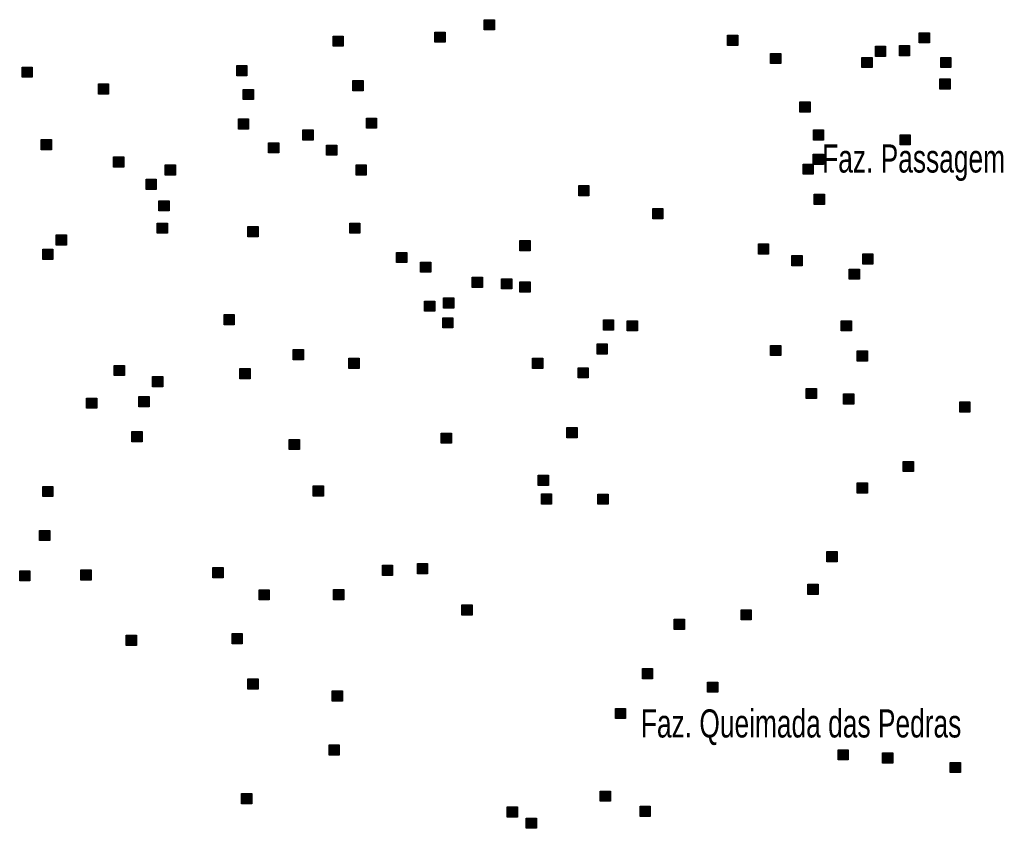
# Model space of a CAD drawing. Extents: x 445.4 to 500, y 8728.7 to 8784.
# Drawn here: x 452.93 to 458.52, y 8728.69 to 8733.29 of the extents above; entities that cross this region are included whole.
import ezdxf

# ---------------------------------------------------------------- set-up
doc = ezdxf.new("R2010")
doc.units = 0
doc.header["$LTSCALE"] = 0.064
doc.layers.add('2', color=7, linetype='Continuous', lineweight=25)
doc.layers.add('61', color=7, linetype='Continuous')

msp = doc.modelspace()

# ---------------------------------------------------------------- hatches: boundary and pattern name
at = {"layer": '2'}
for points in [[(455.5694, 8733.2875), (455.6274, 8733.2875), (455.6274, 8733.2295), (455.5694, 8733.2295)], [(454.7097, 8733.1942), (454.7677, 8733.1942), (454.7677, 8733.1362), (454.7097, 8733.1362)], [(455.2889, 8733.2168), (455.3469, 8733.2168), (455.3469, 8733.1588), (455.2889, 8733.1588)], [(456.9541, 8733.1994), (457.0121, 8733.1994), (457.0121, 8733.1414), (456.9541, 8733.1414)], [(458.0446, 8733.213), (458.1026, 8733.213), (458.1026, 8733.155), (458.0446, 8733.155)], [(457.7957, 8733.1361), (457.8537, 8733.1361), (457.8537, 8733.0781), (457.7957, 8733.0781)], [(457.9315, 8733.1406), (457.9895, 8733.1406), (457.9895, 8733.0826), (457.9315, 8733.0826)], [(457.1984, 8733.0953), (457.2564, 8733.0953), (457.2564, 8733.0373), (457.1984, 8733.0373)], [(454.1622, 8733.0266), (454.2202, 8733.0266), (454.2202, 8732.9686), (454.1622, 8732.9686)], [(457.7188, 8733.0727), (457.7768, 8733.0727), (457.7768, 8733.0147), (457.7188, 8733.0147)], [(458.1668, 8733.0727), (458.2248, 8733.0727), (458.2248, 8733.0147), (458.1668, 8733.0147)], [(452.9406, 8733.0176), (452.9986, 8733.0176), (452.9986, 8732.9596), (452.9406, 8732.9596)], [(453.3749, 8732.9225), (453.4329, 8732.9225), (453.4329, 8732.8645), (453.3749, 8732.8645)], [(454.8229, 8732.9406), (454.8809, 8732.9406), (454.8809, 8732.8826), (454.8229, 8732.8826)], [(458.1623, 8732.9504), (458.2203, 8732.9504), (458.2203, 8732.8924), (458.1623, 8732.8924)], [(454.1984, 8732.8908), (454.2564, 8732.8908), (454.2564, 8732.8328), (454.1984, 8732.8328)], [(457.3659, 8732.8191), (457.4239, 8732.8191), (457.4239, 8732.7611), (457.3659, 8732.7611)], [(454.1713, 8732.7233), (454.2293, 8732.7233), (454.2293, 8732.6653), (454.1713, 8732.6653)], [(454.8998, 8732.7278), (454.9578, 8732.7278), (454.9578, 8732.6698), (454.8998, 8732.6698)], [(454.5378, 8732.6599), (454.5958, 8732.6599), (454.5958, 8732.6019), (454.5378, 8732.6019)], [(457.4428, 8732.6607), (457.5008, 8732.6607), (457.5008, 8732.6027), (457.4428, 8732.6027)], [(457.9354, 8732.6324), (457.9934, 8732.6324), (457.9934, 8732.5744), (457.9354, 8732.5744)], [(453.0492, 8732.6056), (453.1072, 8732.6056), (453.1072, 8732.5476), (453.0492, 8732.5476)], [(454.3432, 8732.5875), (454.4012, 8732.5875), (454.4012, 8732.5295), (454.3432, 8732.5295)], [(454.6735, 8732.5739), (454.7315, 8732.5739), (454.7315, 8732.5159), (454.6735, 8732.5159)], [(457.4413, 8732.5219), (457.4993, 8732.5219), (457.4993, 8732.4639), (457.4413, 8732.4639)], [(453.4609, 8732.506), (453.5189, 8732.506), (453.5189, 8732.448), (453.4609, 8732.448)], [(457.384, 8732.466), (457.442, 8732.466), (457.442, 8732.408), (457.384, 8732.408)], [(453.755, 8732.4607), (453.813, 8732.4607), (453.813, 8732.4027), (453.755, 8732.4027)], [(454.841, 8732.4607), (454.899, 8732.4607), (454.899, 8732.4027), (454.841, 8732.4027)], [(453.6464, 8732.3792), (453.7044, 8732.3792), (453.7044, 8732.3212), (453.6464, 8732.3212)], [(456.1079, 8732.3438), (456.1659, 8732.3438), (456.1659, 8732.2858), (456.1079, 8732.2858)], [(453.7188, 8732.257), (453.7768, 8732.257), (453.7768, 8732.199), (453.7188, 8732.199)], [(457.4473, 8732.294), (457.5053, 8732.294), (457.5053, 8732.236), (457.4473, 8732.236)], [(456.5287, 8732.2125), (456.5867, 8732.2125), (456.5867, 8732.1545), (456.5287, 8732.1545)], [(453.7098, 8732.1302), (453.7678, 8732.1302), (453.7678, 8732.0722), (453.7098, 8732.0722)], [(454.8048, 8732.1302), (454.8628, 8732.1302), (454.8628, 8732.0722), (454.8048, 8732.0722)], [(454.2258, 8732.1099), (454.2838, 8732.1099), (454.2838, 8732.0519), (454.2258, 8732.0519)], [(453.1351, 8732.0623), (453.1931, 8732.0623), (453.1931, 8732.0043), (453.1351, 8732.0043)], [(455.773, 8732.0306), (455.831, 8732.0306), (455.831, 8731.9726), (455.773, 8731.9726)], [(453.0582, 8731.9808), (453.1162, 8731.9808), (453.1162, 8731.9228), (453.0582, 8731.9228)], [(455.0717, 8731.9627), (455.1297, 8731.9627), (455.1297, 8731.9047), (455.0717, 8731.9047)], [(457.1296, 8732.0111), (457.1876, 8732.0111), (457.1876, 8731.9531), (457.1296, 8731.9531)], [(455.2075, 8731.9084), (455.2655, 8731.9084), (455.2655, 8731.8504), (455.2075, 8731.8504)], [(457.3206, 8731.9453), (457.3786, 8731.9453), (457.3786, 8731.8873), (457.3206, 8731.8873)], [(457.7233, 8731.9544), (457.7813, 8731.9544), (457.7813, 8731.8964), (457.7233, 8731.8964)], [(457.6464, 8731.8684), (457.7044, 8731.8684), (457.7044, 8731.8104), (457.6464, 8731.8104)], [(455.5016, 8731.8223), (455.5596, 8731.8223), (455.5596, 8731.7643), (455.5016, 8731.7643)], [(455.669, 8731.8133), (455.727, 8731.8133), (455.727, 8731.7553), (455.669, 8731.7553)], [(455.773, 8731.7952), (455.831, 8731.7952), (455.831, 8731.7372), (455.773, 8731.7372)], [(455.2301, 8731.6865), (455.2881, 8731.6865), (455.2881, 8731.6285), (455.2301, 8731.6285)], [(455.3387, 8731.7046), (455.3967, 8731.7046), (455.3967, 8731.6466), (455.3387, 8731.6466)], [(454.0899, 8731.6096), (454.1479, 8731.6096), (454.1479, 8731.5516), (454.0899, 8731.5516)], [(455.3341, 8731.5914), (455.3921, 8731.5914), (455.3921, 8731.5334), (455.3341, 8731.5334)], [(456.2482, 8731.5786), (456.3062, 8731.5786), (456.3062, 8731.5206), (456.2482, 8731.5206)], [(456.3839, 8731.5741), (456.4419, 8731.5741), (456.4419, 8731.5161), (456.3839, 8731.5161)], [(457.6012, 8731.5741), (457.6592, 8731.5741), (457.6592, 8731.5161), (457.6012, 8731.5161)], [(454.4835, 8731.4103), (454.5415, 8731.4103), (454.5415, 8731.3523), (454.4835, 8731.3523)], [(456.212, 8731.4428), (456.27, 8731.4428), (456.27, 8731.3848), (456.212, 8731.3848)], [(457.1984, 8731.4337), (457.2564, 8731.4337), (457.2564, 8731.3757), (457.1984, 8731.3757)], [(457.6917, 8731.4021), (457.7497, 8731.4021), (457.7497, 8731.3441), (457.6917, 8731.3441)], [(454.8002, 8731.3605), (454.8582, 8731.3605), (454.8582, 8731.3025), (454.8002, 8731.3025)], [(455.8454, 8731.3605), (455.9034, 8731.3605), (455.9034, 8731.3025), (455.8454, 8731.3025)], [(453.4654, 8731.3198), (453.5234, 8731.3198), (453.5234, 8731.2618), (453.4654, 8731.2618)], [(454.1803, 8731.3017), (454.2383, 8731.3017), (454.2383, 8731.2437), (454.1803, 8731.2437)], [(456.1034, 8731.307), (456.1614, 8731.307), (456.1614, 8731.249), (456.1034, 8731.249)], [(453.6826, 8731.2564), (453.7406, 8731.2564), (453.7406, 8731.1984), (453.6826, 8731.1984)], [(457.4021, 8731.1893), (457.4601, 8731.1893), (457.4601, 8731.1313), (457.4021, 8731.1313)], [(453.3071, 8731.1342), (453.3651, 8731.1342), (453.3651, 8731.0762), (453.3071, 8731.0762)], [(453.6057, 8731.1432), (453.6637, 8731.1432), (453.6637, 8731.0852), (453.6057, 8731.0852)], [(457.6147, 8731.1576), (457.6727, 8731.1576), (457.6727, 8731.0996), (457.6147, 8731.0996)], [(458.2754, 8731.1123), (458.3334, 8731.1123), (458.3334, 8731.0543), (458.2754, 8731.0543)], [(456.04, 8730.9667), (456.098, 8730.9667), (456.098, 8730.9087), (456.04, 8730.9087)], [(453.565, 8730.944), (453.623, 8730.944), (453.623, 8730.886), (453.565, 8730.886)], [(454.4609, 8730.8987), (454.5189, 8730.8987), (454.5189, 8730.8407), (454.4609, 8730.8407)], [(455.3251, 8730.935), (455.3831, 8730.935), (455.3831, 8730.877), (455.3251, 8730.877)], [(457.9541, 8730.7737), (458.0121, 8730.7737), (458.0121, 8730.7157), (457.9541, 8730.7157)], [(455.8771, 8730.695), (455.9351, 8730.695), (455.9351, 8730.637), (455.8771, 8730.637)], [(453.0582, 8730.6316), (453.1162, 8730.6316), (453.1162, 8730.5736), (453.0582, 8730.5736)], [(454.5966, 8730.6344), (454.6546, 8730.6344), (454.6546, 8730.5764), (454.5966, 8730.5764)], [(457.6917, 8730.6515), (457.7497, 8730.6515), (457.7497, 8730.5935), (457.6917, 8730.5935)], [(455.8952, 8730.5891), (455.9532, 8730.5891), (455.9532, 8730.5311), (455.8952, 8730.5311)], [(456.2165, 8730.5881), (456.2745, 8730.5881), (456.2745, 8730.5301), (456.2165, 8730.5301)], [(453.0401, 8730.3808), (453.0981, 8730.3808), (453.0981, 8730.3228), (453.0401, 8730.3228)], [(457.5197, 8730.2604), (457.5777, 8730.2604), (457.5777, 8730.2024), (457.5197, 8730.2024)], [(454.9903, 8730.1834), (455.0483, 8730.1834), (455.0483, 8730.1254), (454.9903, 8730.1254)], [(455.1894, 8730.1925), (455.2474, 8730.1925), (455.2474, 8730.1345), (455.1894, 8730.1345)], [(452.927, 8730.1517), (452.985, 8730.1517), (452.985, 8730.0937), (452.927, 8730.0937)], [(453.2754, 8730.1562), (453.3334, 8730.1562), (453.3334, 8730.0982), (453.2754, 8730.0982)], [(454.0265, 8730.1698), (454.0845, 8730.1698), (454.0845, 8730.1118), (454.0265, 8730.1118)], [(457.4111, 8730.0747), (457.4691, 8730.0747), (457.4691, 8730.0167), (457.4111, 8730.0167)], [(454.2889, 8730.0431), (454.3469, 8730.0431), (454.3469, 8729.9851), (454.2889, 8729.9851)], [(454.713, 8730.0445), (454.771, 8730.0445), (454.771, 8729.9865), (454.713, 8729.9865)], [(455.4427, 8729.957), (455.5007, 8729.957), (455.5007, 8729.899), (455.4427, 8729.899)], [(457.031, 8729.9298), (457.089, 8729.9298), (457.089, 8729.8718), (457.031, 8729.8718)], [(456.6509, 8729.8755), (456.7089, 8729.8755), (456.7089, 8729.8175), (456.6509, 8729.8175)], [(453.5333, 8729.785), (453.5913, 8729.785), (453.5913, 8729.727), (453.5333, 8729.727)], [(454.1351, 8729.7941), (454.1931, 8729.7941), (454.1931, 8729.7361), (454.1351, 8729.7361)], [(456.4699, 8729.5948), (456.5279, 8729.5948), (456.5279, 8729.5368), (456.4699, 8729.5368)], [(454.2256, 8729.536), (454.2836, 8729.536), (454.2836, 8729.478), (454.2256, 8729.478)], [(456.841, 8729.5179), (456.899, 8729.5179), (456.899, 8729.4599), (456.841, 8729.4599)], [(454.7052, 8729.4681), (454.7632, 8729.4681), (454.7632, 8729.4101), (454.7052, 8729.4101)], [(456.3161, 8729.3684), (456.3741, 8729.3684), (456.3741, 8729.3104), (456.3161, 8729.3104)], [(454.6871, 8729.1602), (454.7451, 8729.1602), (454.7451, 8729.1022), (454.6871, 8729.1022)], [(457.5831, 8729.133), (457.6411, 8729.133), (457.6411, 8729.075), (457.5831, 8729.075)], [(457.8365, 8729.1149), (457.8945, 8729.1149), (457.8945, 8729.0569), (457.8365, 8729.0569)], [(458.2211, 8729.0606), (458.2791, 8729.0606), (458.2791, 8729.0026), (458.2211, 8729.0026)], [(454.1894, 8728.884), (454.2474, 8728.884), (454.2474, 8728.826), (454.1894, 8728.826)], [(456.2301, 8728.8976), (456.2881, 8728.8976), (456.2881, 8728.8396), (456.2301, 8728.8396)], [(455.7006, 8728.8071), (455.7586, 8728.8071), (455.7586, 8728.7491), (455.7006, 8728.7491)], [(456.4563, 8728.8116), (456.5143, 8728.8116), (456.5143, 8728.7536), (456.4563, 8728.7536)], [(455.8092, 8728.7437), (455.8672, 8728.7437), (455.8672, 8728.6857), (455.8092, 8728.6857)]]:
    msp.add_hatch(color=256, dxfattribs=at).paths.add_polyline_path(points)

# ---------------------------------------------------------------- linework, layer by layer
for points in [[(455.5694, 8733.2875), (455.6274, 8733.2875), (455.6274, 8733.2295), (455.5694, 8733.2295)], [(454.7097, 8733.1942), (454.7677, 8733.1942), (454.7677, 8733.1362), (454.7097, 8733.1362)], [(455.2889, 8733.2168), (455.3469, 8733.2168), (455.3469, 8733.1588), (455.2889, 8733.1588)], [(456.9541, 8733.1994), (457.0121, 8733.1994), (457.0121, 8733.1414), (456.9541, 8733.1414)], [(458.0446, 8733.213), (458.1026, 8733.213), (458.1026, 8733.155), (458.0446, 8733.155)], [(457.7957, 8733.1361), (457.8537, 8733.1361), (457.8537, 8733.0781), (457.7957, 8733.0781)], [(457.9315, 8733.1406), (457.9895, 8733.1406), (457.9895, 8733.0826), (457.9315, 8733.0826)], [(457.1984, 8733.0953), (457.2564, 8733.0953), (457.2564, 8733.0373), (457.1984, 8733.0373)], [(454.1622, 8733.0266), (454.2202, 8733.0266), (454.2202, 8732.9686), (454.1622, 8732.9686)], [(457.7188, 8733.0727), (457.7768, 8733.0727), (457.7768, 8733.0147), (457.7188, 8733.0147)], [(458.1668, 8733.0727), (458.2248, 8733.0727), (458.2248, 8733.0147), (458.1668, 8733.0147)], [(452.9406, 8733.0176), (452.9986, 8733.0176), (452.9986, 8732.9596), (452.9406, 8732.9596)], [(453.3749, 8732.9225), (453.4329, 8732.9225), (453.4329, 8732.8645), (453.3749, 8732.8645)], [(454.8229, 8732.9406), (454.8809, 8732.9406), (454.8809, 8732.8826), (454.8229, 8732.8826)], [(458.1623, 8732.9504), (458.2203, 8732.9504), (458.2203, 8732.8924), (458.1623, 8732.8924)], [(454.1984, 8732.8908), (454.2564, 8732.8908), (454.2564, 8732.8328), (454.1984, 8732.8328)], [(457.3659, 8732.8191), (457.4239, 8732.8191), (457.4239, 8732.7611), (457.3659, 8732.7611)], [(454.1713, 8732.7233), (454.2293, 8732.7233), (454.2293, 8732.6653), (454.1713, 8732.6653)], [(454.8998, 8732.7278), (454.9578, 8732.7278), (454.9578, 8732.6698), (454.8998, 8732.6698)], [(454.5378, 8732.6599), (454.5958, 8732.6599), (454.5958, 8732.6019), (454.5378, 8732.6019)], [(457.4428, 8732.6607), (457.5008, 8732.6607), (457.5008, 8732.6027), (457.4428, 8732.6027)], [(457.9354, 8732.6324), (457.9934, 8732.6324), (457.9934, 8732.5744), (457.9354, 8732.5744)], [(453.0492, 8732.6056), (453.1072, 8732.6056), (453.1072, 8732.5476), (453.0492, 8732.5476)], [(454.3432, 8732.5875), (454.4012, 8732.5875), (454.4012, 8732.5295), (454.3432, 8732.5295)], [(454.6735, 8732.5739), (454.7315, 8732.5739), (454.7315, 8732.5159), (454.6735, 8732.5159)], [(457.4413, 8732.5219), (457.4993, 8732.5219), (457.4993, 8732.4639), (457.4413, 8732.4639)], [(453.4609, 8732.506), (453.5189, 8732.506), (453.5189, 8732.448), (453.4609, 8732.448)], [(457.384, 8732.466), (457.442, 8732.466), (457.442, 8732.408), (457.384, 8732.408)], [(453.755, 8732.4607), (453.813, 8732.4607), (453.813, 8732.4027), (453.755, 8732.4027)], [(454.841, 8732.4607), (454.899, 8732.4607), (454.899, 8732.4027), (454.841, 8732.4027)], [(453.6464, 8732.3792), (453.7044, 8732.3792), (453.7044, 8732.3212), (453.6464, 8732.3212)], [(456.1079, 8732.3438), (456.1659, 8732.3438), (456.1659, 8732.2858), (456.1079, 8732.2858)], [(453.7188, 8732.257), (453.7768, 8732.257), (453.7768, 8732.199), (453.7188, 8732.199)], [(457.4473, 8732.294), (457.5053, 8732.294), (457.5053, 8732.236), (457.4473, 8732.236)], [(456.5287, 8732.2125), (456.5867, 8732.2125), (456.5867, 8732.1545), (456.5287, 8732.1545)], [(453.7098, 8732.1302), (453.7678, 8732.1302), (453.7678, 8732.0722), (453.7098, 8732.0722)], [(454.8048, 8732.1302), (454.8628, 8732.1302), (454.8628, 8732.0722), (454.8048, 8732.0722)], [(454.2258, 8732.1099), (454.2838, 8732.1099), (454.2838, 8732.0519), (454.2258, 8732.0519)], [(453.1351, 8732.0623), (453.1931, 8732.0623), (453.1931, 8732.0043), (453.1351, 8732.0043)], [(455.773, 8732.0306), (455.831, 8732.0306), (455.831, 8731.9726), (455.773, 8731.9726)], [(453.0582, 8731.9808), (453.1162, 8731.9808), (453.1162, 8731.9228), (453.0582, 8731.9228)], [(455.0717, 8731.9627), (455.1297, 8731.9627), (455.1297, 8731.9047), (455.0717, 8731.9047)], [(457.1296, 8732.0111), (457.1876, 8732.0111), (457.1876, 8731.9531), (457.1296, 8731.9531)], [(455.2075, 8731.9084), (455.2655, 8731.9084), (455.2655, 8731.8504), (455.2075, 8731.8504)], [(457.3206, 8731.9453), (457.3786, 8731.9453), (457.3786, 8731.8873), (457.3206, 8731.8873)], [(457.7233, 8731.9544), (457.7813, 8731.9544), (457.7813, 8731.8964), (457.7233, 8731.8964)], [(457.6464, 8731.8684), (457.7044, 8731.8684), (457.7044, 8731.8104), (457.6464, 8731.8104)], [(455.5016, 8731.8223), (455.5596, 8731.8223), (455.5596, 8731.7643), (455.5016, 8731.7643)], [(455.669, 8731.8133), (455.727, 8731.8133), (455.727, 8731.7553), (455.669, 8731.7553)], [(455.773, 8731.7952), (455.831, 8731.7952), (455.831, 8731.7372), (455.773, 8731.7372)], [(455.2301, 8731.6865), (455.2881, 8731.6865), (455.2881, 8731.6285), (455.2301, 8731.6285)], [(455.3387, 8731.7046), (455.3967, 8731.7046), (455.3967, 8731.6466), (455.3387, 8731.6466)], [(454.0899, 8731.6096), (454.1479, 8731.6096), (454.1479, 8731.5516), (454.0899, 8731.5516)], [(455.3341, 8731.5914), (455.3921, 8731.5914), (455.3921, 8731.5334), (455.3341, 8731.5334)], [(456.2482, 8731.5786), (456.3062, 8731.5786), (456.3062, 8731.5206), (456.2482, 8731.5206)], [(456.3839, 8731.5741), (456.4419, 8731.5741), (456.4419, 8731.5161), (456.3839, 8731.5161)], [(457.6012, 8731.5741), (457.6592, 8731.5741), (457.6592, 8731.5161), (457.6012, 8731.5161)], [(454.4835, 8731.4103), (454.5415, 8731.4103), (454.5415, 8731.3523), (454.4835, 8731.3523)], [(456.212, 8731.4428), (456.27, 8731.4428), (456.27, 8731.3848), (456.212, 8731.3848)], [(457.1984, 8731.4337), (457.2564, 8731.4337), (457.2564, 8731.3757), (457.1984, 8731.3757)], [(457.6917, 8731.4021), (457.7497, 8731.4021), (457.7497, 8731.3441), (457.6917, 8731.3441)], [(454.8002, 8731.3605), (454.8582, 8731.3605), (454.8582, 8731.3025), (454.8002, 8731.3025)], [(455.8454, 8731.3605), (455.9034, 8731.3605), (455.9034, 8731.3025), (455.8454, 8731.3025)], [(453.4654, 8731.3198), (453.5234, 8731.3198), (453.5234, 8731.2618), (453.4654, 8731.2618)], [(454.1803, 8731.3017), (454.2383, 8731.3017), (454.2383, 8731.2437), (454.1803, 8731.2437)], [(456.1034, 8731.307), (456.1614, 8731.307), (456.1614, 8731.249), (456.1034, 8731.249)], [(453.6826, 8731.2564), (453.7406, 8731.2564), (453.7406, 8731.1984), (453.6826, 8731.1984)], [(457.4021, 8731.1893), (457.4601, 8731.1893), (457.4601, 8731.1313), (457.4021, 8731.1313)], [(453.3071, 8731.1342), (453.3651, 8731.1342), (453.3651, 8731.0762), (453.3071, 8731.0762)], [(453.6057, 8731.1432), (453.6637, 8731.1432), (453.6637, 8731.0852), (453.6057, 8731.0852)], [(457.6147, 8731.1576), (457.6727, 8731.1576), (457.6727, 8731.0996), (457.6147, 8731.0996)], [(458.2754, 8731.1123), (458.3334, 8731.1123), (458.3334, 8731.0543), (458.2754, 8731.0543)], [(456.04, 8730.9667), (456.098, 8730.9667), (456.098, 8730.9087), (456.04, 8730.9087)], [(453.565, 8730.944), (453.623, 8730.944), (453.623, 8730.886), (453.565, 8730.886)], [(454.4609, 8730.8987), (454.5189, 8730.8987), (454.5189, 8730.8407), (454.4609, 8730.8407)], [(455.3251, 8730.935), (455.3831, 8730.935), (455.3831, 8730.877), (455.3251, 8730.877)], [(457.9541, 8730.7737), (458.0121, 8730.7737), (458.0121, 8730.7157), (457.9541, 8730.7157)], [(455.8771, 8730.695), (455.9351, 8730.695), (455.9351, 8730.637), (455.8771, 8730.637)], [(453.0582, 8730.6316), (453.1162, 8730.6316), (453.1162, 8730.5736), (453.0582, 8730.5736)], [(454.5966, 8730.6344), (454.6546, 8730.6344), (454.6546, 8730.5764), (454.5966, 8730.5764)], [(457.6917, 8730.6515), (457.7497, 8730.6515), (457.7497, 8730.5935), (457.6917, 8730.5935)], [(455.8952, 8730.5891), (455.9532, 8730.5891), (455.9532, 8730.5311), (455.8952, 8730.5311)], [(456.2165, 8730.5881), (456.2745, 8730.5881), (456.2745, 8730.5301), (456.2165, 8730.5301)], [(453.0401, 8730.3808), (453.0981, 8730.3808), (453.0981, 8730.3228), (453.0401, 8730.3228)], [(457.5197, 8730.2604), (457.5777, 8730.2604), (457.5777, 8730.2024), (457.5197, 8730.2024)], [(454.9903, 8730.1834), (455.0483, 8730.1834), (455.0483, 8730.1254), (454.9903, 8730.1254)], [(455.1894, 8730.1925), (455.2474, 8730.1925), (455.2474, 8730.1345), (455.1894, 8730.1345)], [(452.927, 8730.1517), (452.985, 8730.1517), (452.985, 8730.0937), (452.927, 8730.0937)], [(453.2754, 8730.1562), (453.3334, 8730.1562), (453.3334, 8730.0982), (453.2754, 8730.0982)], [(454.0265, 8730.1698), (454.0845, 8730.1698), (454.0845, 8730.1118), (454.0265, 8730.1118)], [(457.4111, 8730.0747), (457.4691, 8730.0747), (457.4691, 8730.0167), (457.4111, 8730.0167)], [(454.2889, 8730.0431), (454.3469, 8730.0431), (454.3469, 8729.9851), (454.2889, 8729.9851)], [(454.713, 8730.0445), (454.771, 8730.0445), (454.771, 8729.9865), (454.713, 8729.9865)], [(455.4427, 8729.957), (455.5007, 8729.957), (455.5007, 8729.899), (455.4427, 8729.899)], [(457.031, 8729.9298), (457.089, 8729.9298), (457.089, 8729.8718), (457.031, 8729.8718)], [(456.6509, 8729.8755), (456.7089, 8729.8755), (456.7089, 8729.8175), (456.6509, 8729.8175)], [(453.5333, 8729.785), (453.5913, 8729.785), (453.5913, 8729.727), (453.5333, 8729.727)], [(454.1351, 8729.7941), (454.1931, 8729.7941), (454.1931, 8729.7361), (454.1351, 8729.7361)], [(456.4699, 8729.5948), (456.5279, 8729.5948), (456.5279, 8729.5368), (456.4699, 8729.5368)], [(454.2256, 8729.536), (454.2836, 8729.536), (454.2836, 8729.478), (454.2256, 8729.478)], [(456.841, 8729.5179), (456.899, 8729.5179), (456.899, 8729.4599), (456.841, 8729.4599)], [(454.7052, 8729.4681), (454.7632, 8729.4681), (454.7632, 8729.4101), (454.7052, 8729.4101)], [(456.3161, 8729.3684), (456.3741, 8729.3684), (456.3741, 8729.3104), (456.3161, 8729.3104)], [(454.6871, 8729.1602), (454.7451, 8729.1602), (454.7451, 8729.1022), (454.6871, 8729.1022)], [(457.5831, 8729.133), (457.6411, 8729.133), (457.6411, 8729.075), (457.5831, 8729.075)], [(457.8365, 8729.1149), (457.8945, 8729.1149), (457.8945, 8729.0569), (457.8365, 8729.0569)], [(458.2211, 8729.0606), (458.2791, 8729.0606), (458.2791, 8729.0026), (458.2211, 8729.0026)], [(454.1894, 8728.884), (454.2474, 8728.884), (454.2474, 8728.826), (454.1894, 8728.826)], [(456.2301, 8728.8976), (456.2881, 8728.8976), (456.2881, 8728.8396), (456.2301, 8728.8396)], [(455.7006, 8728.8071), (455.7586, 8728.8071), (455.7586, 8728.7491), (455.7006, 8728.7491)], [(456.4563, 8728.8116), (456.5143, 8728.8116), (456.5143, 8728.7536), (456.4563, 8728.7536)], [(455.8092, 8728.7437), (455.8672, 8728.7437), (455.8672, 8728.6857), (455.8092, 8728.6857)]]:
    msp.add_lwpolyline(points, close=True, dxfattribs=at)

# ---------------------------------------------------------------- texts
at = {"layer": '61', "width": 0.7}
for s, p in [('Faz. Passagem', (457.4925, 8732.4175)), ('Faz. Queimada das Pedras', (456.461, 8729.2027))]:
    msp.add_text(s, height=0.16, dxfattribs=at).set_placement(p)

doc.saveas('drawing.dxf')
